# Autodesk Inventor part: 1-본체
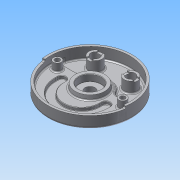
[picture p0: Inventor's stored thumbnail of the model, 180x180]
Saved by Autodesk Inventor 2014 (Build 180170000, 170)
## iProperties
Created: 2015-06
Part Number: 1-본체
Material: 알루미늄 6061
Document SubType Name: Modeling
Designer: Administrator
Density: 2.71 g/cm^3
Appearance: 알루미늄 - 평지
Mass: 1072.06 g
Surface Area: 1037 cm^2
Volume: 395.592 cm^3
Author: Administrator
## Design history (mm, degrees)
sketch "스케치1"
  geometry: C1 r 95 at (0, 0); 1 further point
  constraints: 1 centre point, 1 coincident
  dimensions: "d0" = 190 diameter of C1
extrude "돌출1" new body sketch "스케치1" distance "d1" = 32; taper "d2" = 0 deg
sketch "스케치2"
  geometry: C1 r 95 at (0, 0) reference; C2 r 90 at (0, 0)
  constraints: 1 centre point, 1 coincident
  dimensions: "d3" = 180 diameter of C2
extrude "돌출2" cut sketch "스케치2" distance "d4" = 18; taper "d5" = 0 deg
sketch "스케치3"
  geometry: L1 (-38.833, 16)-(-88.566, 16); L2 (38.833, 16)-(88.566, 16); A1 r 90 centre (0, 0) between (-88.566, 16) and (88.566, 16) reference; A2 r 42 centre (0, 0) between (-38.833, 16) and (38.833, 16)
  constraints: 4 end point, 4 point on circle, 1 centre point, 1 coincident, 1 collinear, 1 horizontal, 1 point on line
  dimensions: "d6" = 84 diameter of A2; "d7" = 16 distance from line of L1 A1.centre
extrude "돌출3" cut sketch "스케치3" distance "d8" = 7; taper "d9" = 0 deg
sketch "스케치4"
  geometry: C1 r 35 at (0, 0); A1 r 42 centre (0, 0) between (38.833, 16) and (-38.833, 16) reference
  constraints: 1 centre point, 1 coincident
  dimensions: "d10" = 70 diameter of C1
extrude "돌출4" join sketch "스케치4" distance "d11" = 10; taper "d12" = -10 deg
sketch "스케치5"
  geometry: L1 (-95, 0)-(95, 0); L2 (0, 0)-(-94.075, -13.221); L3 (0, 0)-(94.075, -13.221); C1 r 90 at (0, 0) reference; A1 r 95 centre (0, 0) between (-95, 0) and (95, 0) reference
  constraints: 6 end point, 4 point on circle, 1 coincident, 1 horizontal, 1 midpoint
  dimensions: "d13" = 8 deg angle of L2 L1; "d14" = 8 deg angle of L3 L1
extrude "돌출5" cut sketch "스케치5" distance "d15" = 5; taper "d16" = 0 deg
sketch "스케치6"
  geometry: L1 (88.566, 16)-(38.833, 16) reference; L2 (-74, 0)-(74, 0); C1 r 35 at (0, 0) reference; C2 r 9 at (-74, 0); C3 r 9 at (74, 0); 1 further point
  constraints: 3 coincident, 2 centre point, 2 end point, 1 midpoint, 1 parallel
  dimensions: "d17" = 148 distance of L2.start L2.end; "d18" = 18 diameter of C2; "d19" = 18 diameter of C3
extrude "돌출6" join sketch "스케치6" stored distance "d20" = 0; taper "d21" = 0 deg
sketch "스케치7"
  geometry: L1 (88.566, 16)-(38.833, 16) reference; L2 (-87.972, -19)-(87.972, -19); L3 (-88.904, -14)-(88.904, -14); L4 (-59, -19)-(-59, -14); L5 (-41, -19)-(-41, -14); L6 (41, -19)-(41, -14); L7 (59, -19)-(59, -14); C1 r 35 at (0, 0) reference; A1 r 90 centre (0, 0) between (-88.566, 16) and (88.566, 16) reference; A2 r 59 centre (0, -19) between (-59, -19) and (59, -19); A3 r 41 centre (0, -19) between (-41, -19) and (41, -19); A4 r 9 centre (-50, -14) between (-41, -14) and (-59, -14); A5 r 9 centre (50, -14) between (59, -14) and (41, -14); 1 further point
  constraints: 12 end point, 11 point on circle, 8 point on line, 8 tangent, 4 centre point, 4 parallel, 2 perpendicular, 1 coincident, 1 midpoint, 1 vertical alignment
  dimensions: "d22" = 118 diameter of A2; "d23" = 19 distance of A2.centre C1.centre; "d24" = 82 diameter of A3; "d25" = 5 distance between parallel lines of L2 L3
extrude "돌출7" cut sketch "스케치7" distance "d26" = 7; taper "d27" = 0 deg
sketch "스케치8"
  geometry: L1 (-38.833, 16)-(-88.566, 16) reference; L2 (-40, 52)-(40, 52); C1 r 15 at (-40, 52); C2 r 15 at (40, 52); A1 r 42 centre (0, 0) between (38.833, 16) and (-38.833, 16) reference; 1 further point
  constraints: 2 centre point, 2 coincident, 2 end point, 1 equal radius, 1 midpoint, 1 parallel, 1 vertical alignment
  dimensions: "d28" = 80 distance of L2.start L2.end; "d29" = 52 distance from line of L2 A1.centre; "d30" = 30 diameter of C1
extrude "돌출8" join sketch "스케치8" stored distance "d31" = 7; taper "d32" = 0 deg
sketch "스케치9"
  geometry: C1 r 95 at (0, 0) reference; C2 r 26 at (0, 0)
  constraints: 1 centre point, 1 coincident
  dimensions: "d33" = 52 diameter of C2
extrude "돌출9" join sketch "스케치9" distance "d34" = 12; taper "d35" = -15 deg
hole "구멍1" diameter "d38" = 23; stored, may be unused: countersink angle "d42" = 90 deg, drill point angle "d44" = 0 deg; dims "d36" = 10, "d37" = 10, "d39" = 6, "d40" = 50, "d41" = 15, "d43" = 8
sketch "스케치10"
  geometry: C1 r 15 at (0, 0) reference; C2 r 15 at (80, 0) reference; 3 further points
  constraints: 2 coincident
hole "구멍2" sketch "스케치10" at (0, 0), (80, 0) diameter "d45" = 20; stored, may be unused: countersink angle "d49" = 90 deg, drill point angle "d51" = 0 deg; dims "d46" = 6, "d47" = 50, "d48" = 15, "d50" = 8
sketch "스케치11"
  geometry: C1 r 9 at (-74, 0) reference; C2 r 9 at (74, 0) reference; 2 further points
  constraints: 2 coincident
hole "구멍3" sketch "스케치11" at (-74, 0), (74, 0) diameter "d52" = 11; stored, may be unused: countersink angle "d56" = 90 deg, drill point angle "d58" = 0 deg; dims "d53" = 6, "d54" = 18, "d55" = 11, "d57" = 8
sketch "스케치12"
  geometry: C1 r 95 at (0, 0) reference; C2 r 68 at (0, 0)
  constraints: 1 centre point, 1 coincident, 1 other
  dimensions: "d59" = 136 diameter of C2
feature "엠보싱1" sketch "스케치12" dims "d60" = 0.5, "d61" = 0
sketch "스케치13"
  geometry: L1 (-6, 13.748)-(-6, -13.748); L2 (6, 13.748)-(6, -13.748); L3 (66.252, 6)-(93.748, 6); L4 (66.252, -6)-(93.748, -6); C1 r 10 at (80, 0) reference; A1 r 15 centre (0, 0) between (-6, 13.748) and (-6, -13.748) reference; A2 r 15 centre (80, 0) between (66.252, 6) and (93.748, 6) reference; 1 further point
  constraints: 8 end point, 8 point on circle, 4 parallel, 1 perpendicular, 1 vertical
  dimensions: "d62" = 12 distance between parallel lines of L2 L1; "d63" = 12 distance between parallel lines of L4 L3
extrude "돌출10" cut sketch "스케치13" distance "d64" = 3; taper "d65" = 0 deg
chamfer "모따기1" distance "d66" = 1; stored, may be unused: second distance "d67" = 2, angle "d68" = 45 deg
fillet "모깎기1" dims "d69" = 10
fillet "모깎기2" dims "d70" = 10
fillet "모깎기3" dims "d71" = 5, "d72" = 1
fillet "모깎기4" dims "d73" = 0.3
fillet "모깎기5" dims "d74" = 3
fillet "모깎기6" dims "d75" = 3
fillet "모깎기7" dims "d76" = 3
node "솔리드1"
node "투영된 루프1"
